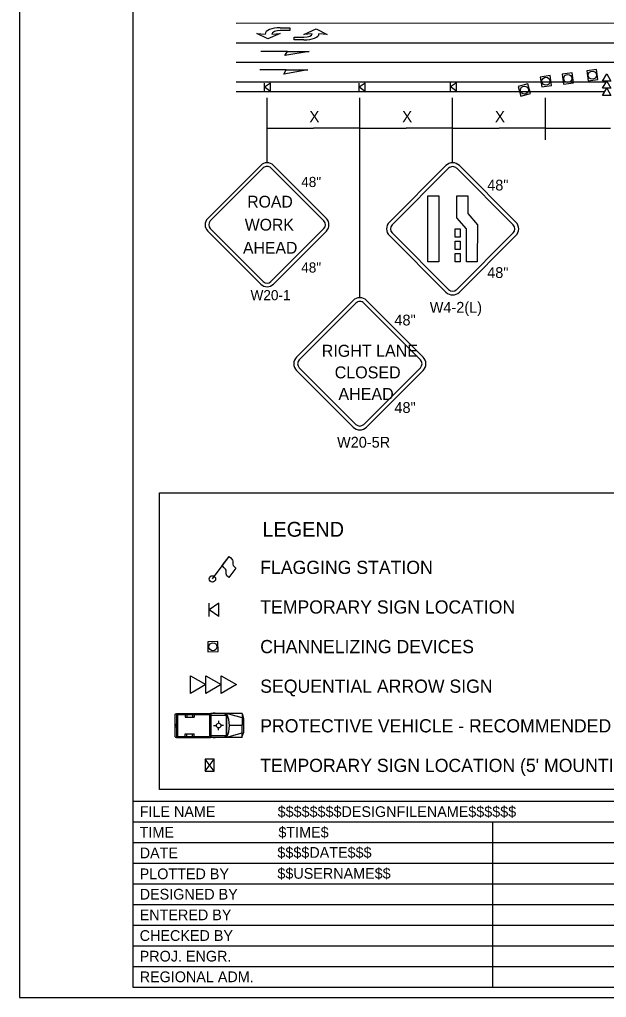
# Model space of a CAD drawing. Extents: x 99988 to 100172, y 99995 to 100047.
# Drawn here: x 99999.31 to 100002.87, y 99999.94 to 100005.86 of the extents above; entities that cross this region are included whole.
import ezdxf

# ---------------------------------------------------------------- set-up
doc = ezdxf.new("R2010")
doc.units = 0
for name, color, linetype in [('Default', 7, 'Continuous'), ('Level 15', 7, 'Continuous'), ('Level 20', 7, 'Continuous'), ('RD_MK_TrafficArrowType2LNew', 7, 'Continuous'), ('SH_DE_DetailBody1Text', 7, 'Continuous'), ('SH_DE_DetailHeading2Text', 7, 'Continuous'), ('SH_GI_PlotLimits', 7, 'Continuous'), ('SH_GI_SheetBorder', 7, 'Continuous'), ('SH_GI_SheetTextInCells', 7, 'Continuous'), ('SH_GI_TitleBlockText', 7, 'Continuous'), ('SH_GI_TrafficMvmntArrowRt1Lane', 7, 'Continuous'), ('SH_TI_SignSpacing35to70Note', 7, 'Continuous'), ('TR_SN_WarningSigns', 7, 'Continuous'), ('TR_WZ_FlaggingStation', 7, 'Continuous'), ('TR_WZ_SequentialArrowTypeC', 7, 'Continuous'), ('TR_WZ_TrafficSafetyCone', 7, 'Continuous'), ('TR_WZ_TruckBuffer', 7, 'Continuous'), ('TR_WZ_WorkZoneDetails', 7, 'Continuous')]:
    doc.layers.add(name, color=color, linetype=linetype)

msp = doc.modelspace()

# ---------------------------------------------------------------- linework, layer by layer
at = {"layer": 'Default'}
for p, q in [((100004.9835, 100005.8415), (100000.6255, 100005.8384)), ((100000.8348, 100005.4779), (100000.7982, 100005.4524)), ((100000.7982, 100005.4269), (100000.7982, 100005.4779)), ((100000.8348, 100005.4269), (100000.7982, 100005.4524)), ((100000.8348, 100005.4269), (100000.8348, 100005.4779)), ((100001.4073, 100005.4779), (100001.3707, 100005.4524)), ((100001.3707, 100005.4269), (100001.3707, 100005.4779)), ((100001.4073, 100005.4269), (100001.3707, 100005.4524)), ((100001.4073, 100005.4269), (100001.4073, 100005.4779)), ((100001.9625, 100005.48), (100001.9259, 100005.4545)), ((100001.9259, 100005.4291), (100001.9259, 100005.48)), ((100001.9625, 100005.4291), (100001.9259, 100005.4545)), ((100001.9625, 100005.4291), (100001.9625, 100005.48)), ((100000.5202, 100002.3264), (100000.4625, 100002.2862)), ((100000.4625, 100002.246), (100000.4625, 100002.3264)), ((100000.5202, 100002.246), (100000.5202, 100002.3264)), ((100000.5202, 100002.246), (100000.4625, 100002.2862)), ((100000.4383, 100001.3092), (100000.4927, 100001.3818)), ((100000.4927, 100001.3092), (100000.4383, 100001.3818)), ((100000.4654, 100001.3454), (100000.4654, 100001.3454)), ((100000.4655, 100001.3455), (100000.4655, 100001.3455))]:
    msp.add_line(p, q, dxfattribs=at)
msp.add_lwpolyline([(100000.4383, 100001.3092), (100000.4927, 100001.3092), (100000.4927, 100001.3818), (100000.4383, 100001.3818)], close=True, dxfattribs=at)
at = {"layer": 'Level 15'}
for p, q in [((100000.8132, 100005.2045), (100001.0945, 100005.2045)), ((100001.3757, 100005.2045), (100001.0945, 100005.2045)), ((100001.3757, 100005.2045), (100001.657, 100005.2045)), ((100001.9382, 100005.2045), (100001.657, 100005.2045)), ((100001.9382, 100005.2045), (100002.2195, 100005.2045)), ((100002.5007, 100005.2045), (100002.2195, 100005.2045)), ((100002.5007, 100005.2045), (100002.8949, 100005.2045))]:
    msp.add_line(p, q, dxfattribs=at)
at = {"layer": 'RD_MK_TrafficArrowType2LNew'}
for p, q in [((100000.893, 100005.8126), (100000.893, 100005.8126)), ((100000.893, 100005.8126), (100000.893, 100005.8126)), ((100000.893, 100005.7959), (100000.893, 100005.7959)), ((100000.8014, 100005.7751), (100000.8014, 100005.7751)), ((100000.843, 100005.7751), (100000.843, 100005.7751)), ((100001.0359, 100005.7397), (100001.0359, 100005.7397)), ((100001.0359, 100005.7397), (100001.0359, 100005.7397)), ((100001.0361, 100005.7564), (100001.0361, 100005.7564)), ((100001.0863, 100005.7767), (100001.0863, 100005.7767)), ((100001.1279, 100005.7763), (100001.1279, 100005.7763))]:
    msp.add_line(p, q, dxfattribs=at)
for points in [[(100000.893, 100005.8126), (100000.9514, 100005.8126), (100000.9514, 100005.7959), (100000.893, 100005.7959)], [(100001.0863, 100005.7767), (100001.0362, 100005.7731), (100001.1116, 100005.8056), (100001.1779, 100005.7716), (100001.1279, 100005.7763)], [(100000.843, 100005.7751), (100000.893, 100005.7792), (100000.818, 100005.7459), (100000.7514, 100005.7792), (100000.8014, 100005.7751)], [(100001.0359, 100005.7397), (100000.9776, 100005.7403), (100000.9777, 100005.757), (100001.0361, 100005.7564)]]:
    msp.add_lwpolyline(points, dxfattribs=at)
for centre, major_axis, ratio, start_param in [((100000.893, 100005.7751), (-0.0917, 0), 0.40879, 4.712524), ((100000.893, 100005.7751), (-0.05, 0), 0.41611, 4.712518), ((100001.0363, 100005.7772), (0.0917, -0.0009), 0.40879, 4.712524), ((100001.0363, 100005.7772), (0.05, -0.0005), 0.41611, 4.712518)]:
    msp.add_ellipse(centre, major_axis=major_axis, ratio=ratio, start_param=start_param, end_param=6.283185, dxfattribs=at)
at = {"layer": 'SH_GI_PlotLimits'}
msp.add_lwpolyline([(99999.3125, 99999.9375), (100015.8125, 99999.9375), (100015.8125, 100010.4375), (99999.3125, 100010.4375)], close=True, dxfattribs=at)
at = {"layer": 'SH_GI_SheetBorder'}
for p, q in [((100000, 100010.375), (100000, 100000)), ((100000, 100001.1259), (100015.75, 100001.1259)), ((100000, 100001.0008), (100007.4566, 100001.0008)), ((100002.179, 100001.0008), (100002.179, 100000)), ((100000, 100000.8757), (100002.1821, 100000.8757)), ((100002.1821, 100000.8757), (100005.4466, 100000.8757)), ((100000, 100000.7506), (100002.1821, 100000.7506)), ((100002.1821, 100000.7506), (100005.4466, 100000.7506)), ((100000, 100000.6255), (100005.4466, 100000.6255)), ((100000, 100000.5004), (100005.4466, 100000.5004)), ((100000, 100000.3753), (100005.4466, 100000.3753)), ((100000, 100000.2502), (100005.4466, 100000.2502)), ((100000, 100000.1251), (100005.4466, 100000.1251)), ((100000, 100000), (100015.75, 100000))]:
    msp.add_line(p, q, dxfattribs=at)
at = {"layer": 'SH_GI_TrafficMvmntArrowRt1Lane'}
for p, q in [((100000.9364, 100005.6701), (100000.7757, 100005.6701)), ((100000.9298, 100005.5577), (100000.7691, 100005.5577))]:
    msp.add_line(p, q, dxfattribs=at)
for points in [[(100001.0675, 100005.6701), (100000.9216, 100005.6444), (100000.9364, 100005.6701)], [(100001.0608, 100005.5577), (100000.915, 100005.532), (100000.9298, 100005.5577)]]:
    msp.add_lwpolyline(points, close=True, dxfattribs=at)
at = {"layer": 'SH_TI_SignSpacing35to70Note'}
msp.add_lwpolyline([(100000.161, 100002.9947), (100003.8408, 100002.9947), (100003.8408, 100001.1965), (100000.161, 100001.1965)], close=True, dxfattribs=at)
at = {"layer": 'TR_SN_WarningSigns'}
for p, q in [((100000.4537, 100004.6578), (100000.775, 100004.9791)), ((100000.469, 100004.6425), (100000.7903, 100004.9637)), ((100000.8362, 100004.9637), (100001.1574, 100004.6425)), ((100000.8515, 100004.9791), (100001.1727, 100004.6578)), ((100001.5547, 100004.6353), (100001.8974, 100004.978)), ((100001.979, 100004.978), (100002.3217, 100004.6353)), ((100001.5711, 100004.619), (100001.9137, 100004.9617)), ((100001.9627, 100004.9617), (100002.3054, 100004.619)), ((100000.775, 100004.26), (100000.4537, 100004.5813)), ((100000.7903, 100004.2753), (100000.469, 100004.5966)), ((100001.1574, 100004.5966), (100000.8362, 100004.2753)), ((100001.1727, 100004.5813), (100000.8515, 100004.26)), ((100001.8974, 100004.2111), (100001.5547, 100004.5537)), ((100001.9137, 100004.2274), (100001.5711, 100004.5701)), ((100002.3054, 100004.5701), (100001.9627, 100004.2274)), ((100002.3217, 100004.5537), (100001.979, 100004.2111)), ((100000.9922, 100003.8176), (100001.3349, 100004.1603)), ((100001.0086, 100003.8013), (100001.3512, 100004.144)), ((100001.4002, 100004.144), (100001.7429, 100003.8013)), ((100001.4165, 100004.1603), (100001.7592, 100003.8176)), ((100001.3349, 100003.3934), (100000.9922, 100003.736)), ((100001.3512, 100003.4097), (100001.0086, 100003.7524)), ((100001.7429, 100003.7524), (100001.4002, 100003.4097)), ((100001.7592, 100003.736), (100001.4165, 100003.3934))]:
    msp.add_line(p, q, dxfattribs=at)
for points in [[(100001.8546, 100004.3945), (100001.7874, 100004.3945), (100001.7874, 100004.7945), (100001.8546, 100004.7945)], [(100002.0306, 100004.7945), (100002.0306, 100004.6866), (100002.089, 100004.6198), (100002.0861, 100004.3945), (100002.0218, 100004.3945), (100002.0218, 100004.5946), (100001.9634, 100004.6614), (100001.9634, 100004.7945)], [(100001.9835, 100004.5445), (100001.9538, 100004.5445), (100001.9538, 100004.5945), (100001.9835, 100004.5945)], [(100001.9835, 100004.4695), (100001.9538, 100004.4695), (100001.9538, 100004.5195), (100001.9835, 100004.5195)], [(100001.9835, 100004.3945), (100001.9538, 100004.3945), (100001.9538, 100004.4445), (100001.9835, 100004.4445)]]:
    msp.add_lwpolyline(points, close=True, dxfattribs=at)
for centre, radius, start, end in [((100000.8132, 100004.9408), 0.0541, 44.99628, 134.99965), ((100000.8132, 100004.9408), 0.0325, 44.99628, 134.99965), ((100001.9382, 100004.9372), 0.0577, 44.99628, 134.99965), ((100001.9382, 100004.9372), 0.0346, 44.99628, 134.99965), ((100000.492, 100004.6195), 0.0541, 134.99658, 224.99358), ((100000.492, 100004.6195), 0.0325, 134.99658, 224.99358), ((100001.1345, 100004.6195), 0.0325, 314.99936, 44.99485), ((100001.1345, 100004.6195), 0.0541, 314.99936, 44.99485), ((100001.5955, 100004.5945), 0.0577, 134.99658, 224.99358), ((100001.5955, 100004.5945), 0.0346, 134.99658, 224.99358), ((100002.2809, 100004.5945), 0.0346, 314.99936, 44.99485), ((100002.2809, 100004.5945), 0.0577, 314.99936, 44.99485), ((100000.8132, 100004.2983), 0.0541, 225, 314.99958), ((100000.8132, 100004.2983), 0.0325, 225, 314.99958), ((100001.9382, 100004.2519), 0.0577, 225, 314.99958), ((100001.9382, 100004.2519), 0.0346, 225, 314.99958), ((100001.3757, 100004.1195), 0.0577, 44.99628, 134.99965), ((100001.3757, 100004.1195), 0.0346, 44.99628, 134.99965), ((100001.033, 100003.7768), 0.0577, 134.99658, 224.99358), ((100001.033, 100003.7768), 0.0346, 134.99658, 224.99358), ((100001.7184, 100003.7768), 0.0346, 314.99936, 44.99485), ((100001.7184, 100003.7768), 0.0577, 314.99936, 44.99485), ((100001.3757, 100003.4342), 0.0577, 225, 314.99958), ((100001.3757, 100003.4342), 0.0346, 225, 314.99958)]:
    msp.add_arc(centre, radius, start, end, dxfattribs=at)
at = {"layer": 'TR_WZ_FlaggingStation'}
for p, q in [((100000.4816, 100002.4732), (100000.5826, 100002.6096)), ((100000.5416, 100002.5542), (100000.5827, 100002.6097)), ((100000.5416, 100002.5542), (100000.5416, 100002.5542)), ((100000.6236, 100002.5391), (100000.5816, 100002.4822))]:
    msp.add_line(p, q, dxfattribs=at)
for points in [[(100000.5827, 100002.6097), (100000.5853, 100002.6073), (100000.5935, 100002.6002), (100000.5994, 100002.5939), (100000.6026, 100002.5878), (100000.6057, 100002.5828), (100000.6066, 100002.5776), (100000.6064, 100002.5722), (100000.6048, 100002.5689), (100000.6049, 100002.5624), (100000.6082, 100002.5553), (100000.6131, 100002.5489), (100000.6236, 100002.5391)], [(100000.5816, 100002.4822), (100000.5777, 100002.4854), (100000.5699, 100002.4931), (100000.565, 100002.5033), (100000.5648, 100002.5107), (100000.5658, 100002.5172), (100000.5643, 100002.5256), (100000.5605, 100002.5321), (100000.5536, 100002.541), (100000.5416, 100002.5542)]]:
    msp.add_lwpolyline(points, dxfattribs=at)
msp.add_circle((100000.4816, 100002.4732), 0.0195, dxfattribs=at)
at = {"layer": 'TR_WZ_SequentialArrowTypeC'}
msp.add_lwpolyline([(100000.3482, 100001.7791), (100000.3482, 100001.8872), (100000.4414, 100001.8331), (100000.4414, 100001.8872), (100000.5348, 100001.8331), (100000.5348, 100001.8872), (100000.628, 100001.8331), (100000.5348, 100001.7791), (100000.5348, 100001.8331), (100000.4414, 100001.7791), (100000.4414, 100001.8331)], close=True, dxfattribs=at)
at = {"layer": 'TR_WZ_TrafficSafetyCone'}
for points in [[(100002.7594, 100005.4914), (100002.8195, 100005.4999), (100002.8111, 100005.56), (100002.7509, 100005.5516)], [(100002.4781, 100005.4545), (100002.5383, 100005.4629), (100002.5298, 100005.5231), (100002.4697, 100005.5146)], [(100002.6107, 100005.4713), (100002.6709, 100005.4797), (100002.6624, 100005.5399), (100002.6023, 100005.5314)], [(100002.352, 100005.3983), (100002.4106, 100005.4141), (100002.3949, 100005.4727), (100002.3363, 100005.457)], [(100000.5147, 100002.0934), (100000.454, 100002.0923), (100000.455, 100002.0316), (100000.5158, 100002.0327)]]:
    msp.add_lwpolyline(points, close=True, dxfattribs=at)
for centre in [(100002.504, 100005.4888), (100002.6366, 100005.5056), (100002.7852, 100005.5257), (100002.3735, 100005.4355), (100000.4849, 100002.0625)]:
    msp.add_circle(centre, 0.0244, dxfattribs=at)
at = {"layer": 'TR_WZ_TruckBuffer'}
for p, q in [((100000.2543, 100001.6514), (100000.2542, 100001.5189)), ((100000.2587, 100001.6559), (100000.2632, 100001.6559)), ((100000.2632, 100001.6559), (100000.2631, 100001.5144)), ((100000.2639, 100001.6583), (100000.2638, 100001.512)), ((100000.2639, 100001.6583), (100000.4696, 100001.6582)), ((100000.2697, 100001.6525), (100000.2697, 100001.5178)), ((100000.2697, 100001.6525), (100000.4638, 100001.6523)), ((100000.3161, 100001.6524), (100000.3161, 100001.6356)), ((100000.3271, 100001.6524), (100000.3271, 100001.6356)), ((100000.3611, 100001.6524), (100000.3611, 100001.6356)), ((100000.371, 100001.6524), (100000.371, 100001.6356)), ((100000.4638, 100001.6523), (100000.4637, 100001.5177)), ((100000.4696, 100001.6582), (100000.4695, 100001.5119)), ((100000.4724, 100001.6582), (100000.4723, 100001.5119)), ((100000.6613, 100001.6581), (100000.4724, 100001.6582)), ((100000.5651, 100001.6468), (100000.4724, 100001.6468)), ((100000.4981, 100001.6602), (100000.4868, 100001.6602)), ((100000.5651, 100001.6581), (100000.5531, 100001.6468)), ((100000.5651, 100001.6581), (100000.565, 100001.5118)), ((100000.5668, 100001.6581), (100000.5667, 100001.5118)), ((100000.6613, 100001.6313), (100000.5668, 100001.6581)), ((100000.6613, 100001.6581), (100000.6612, 100001.5117)), ((100000.6613, 100001.6581), (100000.6705, 100001.6285)), ((100000.2542, 100001.5954), (100000.2632, 100001.5927)), ((100000.2587, 100001.5872), (100000.2587, 100001.5831)), ((100000.3161, 100001.6356), (100000.371, 100001.6356)), ((100000.5197, 100001.614), (100000.5197, 100001.6022)), ((100000.6705, 100001.6285), (100000.6705, 100001.5413)), ((100000.2542, 100001.5748), (100000.2632, 100001.5776)), ((100000.2566, 100001.5851), (100000.2608, 100001.5851)), ((100000.316, 100001.5178), (100000.316, 100001.5346)), ((100000.316, 100001.5346), (100000.371, 100001.5346)), ((100000.327, 100001.5178), (100000.327, 100001.5346)), ((100000.361, 100001.5178), (100000.361, 100001.5346)), ((100000.371, 100001.5178), (100000.371, 100001.5346)), ((100000.4889, 100001.5844), (100000.5037, 100001.5847)), ((100000.5056, 100001.5847), (100000.5056, 100001.5847)), ((100000.519, 100001.5568), (100000.5193, 100001.5678)), ((100000.5499, 100001.5851), (100000.5373, 100001.585)), ((100000.6612, 100001.5385), (100000.5667, 100001.5118)), ((100000.6612, 100001.5849), (100000.5853, 100001.5849)), ((100000.6612, 100001.5117), (100000.6705, 100001.5413)), ((100000.2587, 100001.5144), (100000.2631, 100001.5144)), ((100000.2638, 100001.512), (100000.4695, 100001.5119)), ((100000.2697, 100001.5178), (100000.4637, 100001.5177)), ((100000.565, 100001.5231), (100000.4723, 100001.5232)), ((100000.6612, 100001.5117), (100000.4723, 100001.5119)), ((100000.498, 100001.5098), (100000.4867, 100001.5098)), ((100000.5551, 100001.5231), (100000.565, 100001.5118))]:
    msp.add_line(p, q, dxfattribs=at)
for centre, radius in [((100000.2587, 100001.5851), 0.00206), ((100000.5197, 100001.585), 0.0141)]:
    msp.add_circle(centre, radius, dxfattribs=at)
for centre, radius, start, end in [((100000.2587, 100001.6514), 0.00446, 89.96558, 179.96557), ((100000.4318, 100001.585), 0.1535, 331.51612, 28.42563), ((100000.2587, 100001.5189), 0.00446, 179.96558, 269.96558)]:
    msp.add_arc(centre, radius, start, end, dxfattribs=at)
at = {"layer": 'TR_WZ_WorkZoneDetails'}
for p, q in [((100000.6255, 100005.7212), (100004.3239, 100005.7212)), ((100000.6255, 100005.6038), (100004.9443, 100005.6038)), ((100000.6255, 100005.4863), (100002.8681, 100005.4863)), ((100000.6255, 100005.4276), (100002.8595, 100005.4276)), ((100000.8132, 100004.9949), (100000.8132, 100005.3893)), ((100001.3757, 100004.1772), (100001.3757, 100005.3893)), ((100001.9382, 100004.9949), (100001.9382, 100005.3893)), ((100002.5007, 100005.1345), (100002.5007, 100005.3893))]:
    msp.add_line(p, q, dxfattribs=at)
msp.add_lwpolyline([(100002.898, 100005.4027), (100002.8475, 100005.4027), (100002.8728, 100005.4463), (100002.8475, 100005.4463), (100002.8728, 100005.4899), (100002.8475, 100005.4899), (100002.8728, 100005.5335), (100002.898, 100005.4899), (100002.8728, 100005.4899), (100002.898, 100005.4463), (100002.8728, 100005.4463)], close=True, dxfattribs=at)

# ---------------------------------------------------------------- texts
at = {"layer": 'Level 20'}
for p in [(100001.0689, 100005.2395), (100001.6314, 100005.2395), (100002.1939, 100005.2395)]:
    msp.add_text('X', height=0.07, rotation=360, dxfattribs=at).set_placement(p)
at = {"layer": 'SH_DE_DetailBody1Text'}
for s, p in [('FLAGGING STATION', (100000.7717, 100002.5035)), ('TEMPORARY SIGN LOCATION', (100000.7717, 100002.2635)), ('CHANNELIZING DEVICES', (100000.7717, 100002.0235)), ('SEQUENTIAL ARROW SIGN', (100000.7717, 100001.7835)), ('PROTECTIVE VEHICLE - RECOMMENDED', (100000.7717, 100001.5435)), ("TEMPORARY SIGN LOCATION (5' MOUNTING HEIGHT)", (100000.7717, 100001.3035))]:
    msp.add_text(s, height=0.08, dxfattribs=at).set_placement(p)
at = {"layer": 'SH_DE_DetailHeading2Text'}
msp.add_text('LEGEND', height=0.09, dxfattribs=at).set_placement((100000.7849, 100002.7291))
at = {"layer": 'SH_GI_SheetTextInCells'}
for s, height, p in [('FILE NAME', 0.06505, (100000.041, 100001.0308)), ('TIME', 0.06505, (100000.041, 100000.9057)), ('DATE', 0.06505, (100000.041, 100000.7806)), ('PLOTTED BY', 0.06505, (100000.041, 100000.6538)), ('DESIGNED BY', 0.065052, (100000.041, 100000.5304)), ('ENTERED BY', 0.06505, (100000.041, 100000.4053)), ('CHECKED BY', 0.06505, (100000.041, 100000.2802)), ('PROJ. ENGR.', 0.065052, (100000.041, 100000.1551)), ('REGIONAL ADM.', 0.065052, (100000.041, 100000.03))]:
    msp.add_text(s, height=height, dxfattribs=at).set_placement(p)
at = {"layer": 'SH_GI_TitleBlockText'}
for s, height, p in [('$$$$$$$$DESIGNFILENAME$$$$$$', 0.065052, (100000.8775, 100001.0308)), ('$TIME$', 0.06505, (100000.882, 100000.9059)), ('$$$$DATE$$$', 0.065052, (100000.8759, 100000.7835)), ('$$USERNAME$$', 0.065052, (100000.8759, 100000.6567))]:
    msp.add_text(s, height=height, dxfattribs=at).set_placement(p)
at = {"layer": 'TR_SN_WarningSigns'}
for s, height, p in [('48"', 0.06152, (100001.0203, 100004.8479)), ('48"', 0.06563, (100002.1479, 100004.8269)), ('ROAD', 0.07155, (100000.6928, 100004.7235)), ('WORK', 0.07155, (100000.6781, 100004.5838)), ('AHEAD', 0.07155, (100000.6673, 100004.4441)), ('48"', 0.06152, (100001.0203, 100004.3297)), ('48"', 0.06563, (100002.1479, 100004.2966)), ('W20-1', 0.06152, (100000.7131, 100004.162)), ('W4-2(L)', 0.06563, (100001.7995, 100004.0863)), ('48"', 0.06563, (100001.5854, 100004.0092)), ('RIGHT LANE', 0.07268, (100001.1449, 100003.8193)), ('CLOSED', 0.07268, (100001.2233, 100003.6885)), ('AHEAD', 0.07268, (100001.246, 100003.5577)), ('48"', 0.06563, (100001.5854, 100003.4789)), ('W20-5R', 0.06563, (100001.2375, 100003.2687))]:
    msp.add_text(s, height=height, dxfattribs=at).set_placement(p)

doc.saveas('drawing.dxf')
